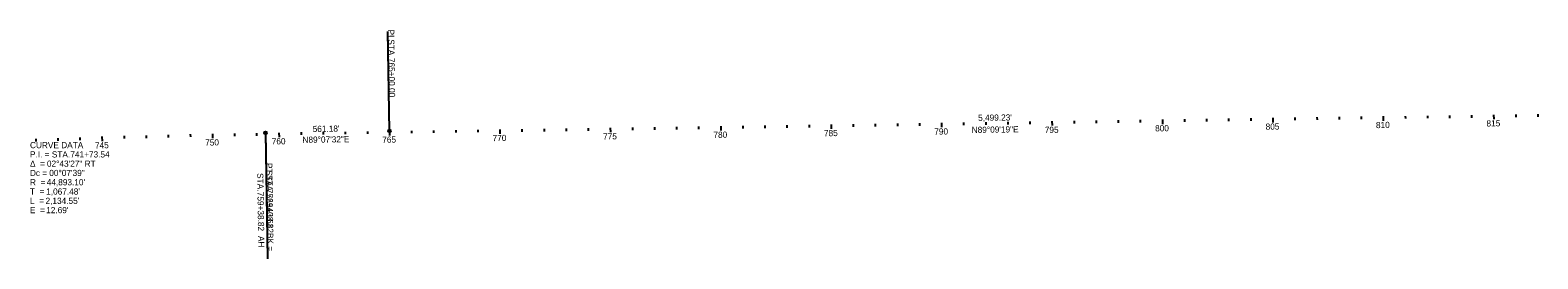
# Model space of a CAD drawing. Extents: x 117326 to 225548, y 573011 to 581051.
# Drawn here: x 191622 to 198448, y 577587 to 578622 of the extents above; entities that cross this region are included whole.
import ezdxf

# ---------------------------------------------------------------- set-up
doc = ezdxf.new("R2010")
doc.units = 0
for name, color, linetype in [('_CIVIL_CONSTRUCTION', 7, 'Continuous'), ('GE_P_Alignment', 7, 'Continuous'), ('GE_P_Alignment_100_Bearings', 7, 'Continuous'), ('GE_P_Alignment_100_Cardinal_Points', 7, 'Continuous'), ('GE_P_Alignment_100_Curve_Data', 7, 'Continuous')]:
    doc.layers.add(name, color=color, linetype=linetype)

msp = doc.modelspace()

# ---------------------------------------------------------------- linework, layer by layer
at = {"layer": 'GE_P_Alignment'}
for p, q in [((193248.2, 578165.8), (193241.5, 578615.7)), ((192687.1, 578157.2), (192693.9, 577707.3)), ((192687.1, 578157.2), (192695.6, 577587.3))]:
    msp.add_line(p, q, dxfattribs=at)
for centre in [(192687.1, 578157.2), (192687.1, 578157.2), (193248.2, 578165.8)]:
    msp.add_circle(centre, 6, dxfattribs=at)
at = {"layer": 'GE_P_Alignment_100_Curve_Data'}
for p, q in [((194548, 578184.9), (194548.2, 578172.9)), ((194648, 578186.4), (194648.2, 578174.4)), ((194748, 578187.9), (194748.3, 578167.9)), ((194848, 578189.4), (194848.2, 578177.4)), ((194948, 578190.8), (194948.2, 578178.8)), ((195048, 578192.3), (195048.2, 578180.3)), ((195148, 578193.8), (195148.1, 578181.8)), ((195248, 578195.2), (195248.3, 578175.3)), ((195348, 578196.7), (195348.1, 578184.7)), ((195447.9, 578198.2), (195448.1, 578186.2)), ((195547.9, 578199.7), (195548.1, 578187.7)), ((195647.9, 578201.1), (195648.1, 578189.1)), ((195747.9, 578202.6), (195748.2, 578182.6)), ((195847.9, 578204.1), (195848.1, 578192.1)), ((195947.9, 578205.6), (195948.1, 578193.6)), ((196047.9, 578207), (196048.1, 578195)), ((196147.9, 578208.5), (196148, 578196.5)), ((196247.9, 578210), (196248.1, 578190)), ((196347.8, 578211.5), (196348, 578199.5)), ((196447.8, 578212.9), (196448, 578200.9)), ((196547.8, 578214.4), (196548, 578202.4)), ((196647.8, 578215.9), (196648, 578203.9)), ((196747.8, 578217.4), (196748.1, 578197.4)), ((196847.8, 578218.8), (196848, 578206.8)), ((196947.8, 578220.3), (196948, 578208.3)), ((197047.8, 578221.8), (197047.9, 578209.8)), ((197147.8, 578223.3), (197147.9, 578211.3)), ((197247.7, 578224.7), (197248, 578204.7)), ((197347.7, 578226.2), (197347.9, 578214.2)), ((197447.7, 578227.7), (197447.9, 578215.7)), ((197547.7, 578229.2), (197547.9, 578217.2)), ((197647.7, 578230.6), (197647.9, 578218.6)), ((197747.7, 578232.1), (197748, 578212.1)), ((197847.7, 578233.6), (197847.9, 578221.6)), ((197947.7, 578235.1), (197947.8, 578223.1)), ((198047.7, 578236.5), (198047.8, 578224.5)), ((198147.6, 578238), (198147.8, 578226)), ((198247.6, 578239.5), (198247.9, 578219.5)), ((198347.6, 578240.9), (198347.8, 578229)), ((198447.6, 578242.4), (198447.8, 578230.4)), ((191646.8, 578129.6), (191647.3, 578117.7)), ((191746.8, 578133.3), (191747.2, 578121.4)), ((191846.7, 578136.8), (191847.1, 578124.8)), ((191946.7, 578140.1), (191947.3, 578120.1)), ((192046.6, 578143.1), (192047, 578131.1)), ((192146.6, 578145.9), (192146.9, 578133.9)), ((192246.5, 578148.5), (192246.8, 578136.5)), ((192346.5, 578150.8), (192346.8, 578138.8)), ((192446.5, 578153), (192446.9, 578133)), ((192546.5, 578154.9), (192546.7, 578142.9)), ((192646.5, 578156.6), (192646.6, 578144.6)), ((192748.2, 578158.1), (192748.5, 578138.1)), ((192848.2, 578159.7), (192848.4, 578147.7)), ((192948.2, 578161.2), (192948.4, 578149.2)), ((193048.2, 578162.7), (193048.4, 578150.7)), ((193148.2, 578164.2), (193148.4, 578152.2)), ((193248.2, 578165.8), (193248.5, 578145.8)), ((193348.2, 578167.2), (193348.3, 578155.2)), ((193448.2, 578168.7), (193448.3, 578156.7)), ((193548.1, 578170.2), (193548.3, 578158.2)), ((193648.1, 578171.7), (193648.3, 578159.7)), ((193748.1, 578173.1), (193748.4, 578153.1)), ((193848.1, 578174.6), (193848.3, 578162.6)), ((193948.1, 578176.1), (193948.3, 578164.1)), ((194048.1, 578177.6), (194048.3, 578165.6)), ((194148.1, 578179), (194148.3, 578167)), ((194248.1, 578180.5), (194248.4, 578160.5)), ((194348.1, 578182), (194348.2, 578170)), ((194448, 578183.5), (194448.2, 578171.5))]:
    msp.add_line(p, q, dxfattribs=at)

# ---------------------------------------------------------------- texts
at = {"layer": '_CIVIL_CONSTRUCTION'}
for s, rotation, p in [('N89°09\'19"E', 0.84468, (195884.6, 578156.6)), ('N89°07\'32"E', 0.87447, (192854.7, 578111.8))]:
    msp.add_text(s, height=28, rotation=rotation, dxfattribs=at).set_placement(p)
at = {"layer": 'GE_P_Alignment'}
for s, rotation, p in [('PI', 270.84468, (193241.8, 578624.7)), (' STA. ', 270.84468, (193242.3, 578590.8)), ('765+00.00', 270.84468, (193243.7, 578496.2)), ('PT', 270.87447, (192689.6, 578020.6)), ('STA. ', 270.85314, (192690, 577988.4)), ('STA. ', 270.85314, (192649.3, 577975.1)), (' STA. ', 270.87447, (192690.2, 577976.5)), ('759+38.82', 270.85314, (192650.5, 577890.5)), ('752+40.61', 270.85314, (192691.3, 577903.8)), ('759+38.82', 270.87447, (192691.7, 577882)), (' AH', 270.85314, (192653.4, 577701)), (' BK =', 270.85314, (192694.1, 577714.3))]:
    msp.add_text(s, height=28, rotation=rotation, dxfattribs=at).set_placement(p)
at = {"layer": 'GE_P_Alignment_100_Bearings'}
for s, p in [('CURVE DATA', (191620.7, 578087.9)), ('P.I. = STA. ', (191620.7, 578045.9)), ('741+73.54', (191803.4, 578045.9)), ('Δ  = ', (191620.7, 578003.9)), ('Dc = ', (191620.7, 577961.9)), ('02°43\'27" RT', (191697.5, 578003.9)), ('00°07\'39"', (191708.1, 577961.9)), ('R  = ', (191620.7, 577919.9)), ("44,893.10'", (191696.5, 577919.9)), ('T  = ', (191620.7, 577877.9)), ('L  = ', (191620.7, 577835.9)), ("2,134.55'", (191691.1, 577835.9)), ("1,067.48'", (191694.1, 577877.9)), ('E  = ', (191620.7, 577793.9)), ("12.69'", (191694.1, 577793.9))]:
    msp.add_text(s, height=28, dxfattribs=at).set_placement(p)
at = {"layer": 'GE_P_Alignment_100_Cardinal_Points'}
for s, rotation, p in [("561.18'", 0.87447, (192900.8, 578160.9)), ("5,499.23'", 0.84468, (195913.9, 578211.3))]:
    msp.add_text(s, height=28, rotation=rotation, dxfattribs=at).set_placement(p)
at = {"layer": 'GE_P_Alignment_100_Curve_Data'}
for s, rotation, p in [('795', 0.84468, (196215.6, 578156.5)), ('800', 0.84468, (196715.1, 578163.9)), ('805', 0.84468, (197215.5, 578171.3)), ('810', 0.84468, (197715, 578178.6)), ('815', 0.84468, (198215.4, 578186)), ('750', 1.16023, (192414.1, 578099.3)), ('760', 0.87447, (192715.6, 578104.6)), ('765', 0.87447, (193215.9, 578112.3)), ('770', 0.84468, (193715.4, 578119.6)), ('775', 0.84468, (194215.8, 578127)), ('780', 0.84468, (194715.3, 578134.4)), ('785', 0.84468, (195215.7, 578141.8)), ('790', 0.84468, (195715.2, 578149.1)), ('745', 1.79836, (191915.3, 578086.1))]:
    msp.add_text(s, height=28, rotation=rotation, dxfattribs=at).set_placement(p)

doc.saveas('drawing.dxf')
